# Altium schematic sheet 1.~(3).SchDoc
size 420 x 297 mm
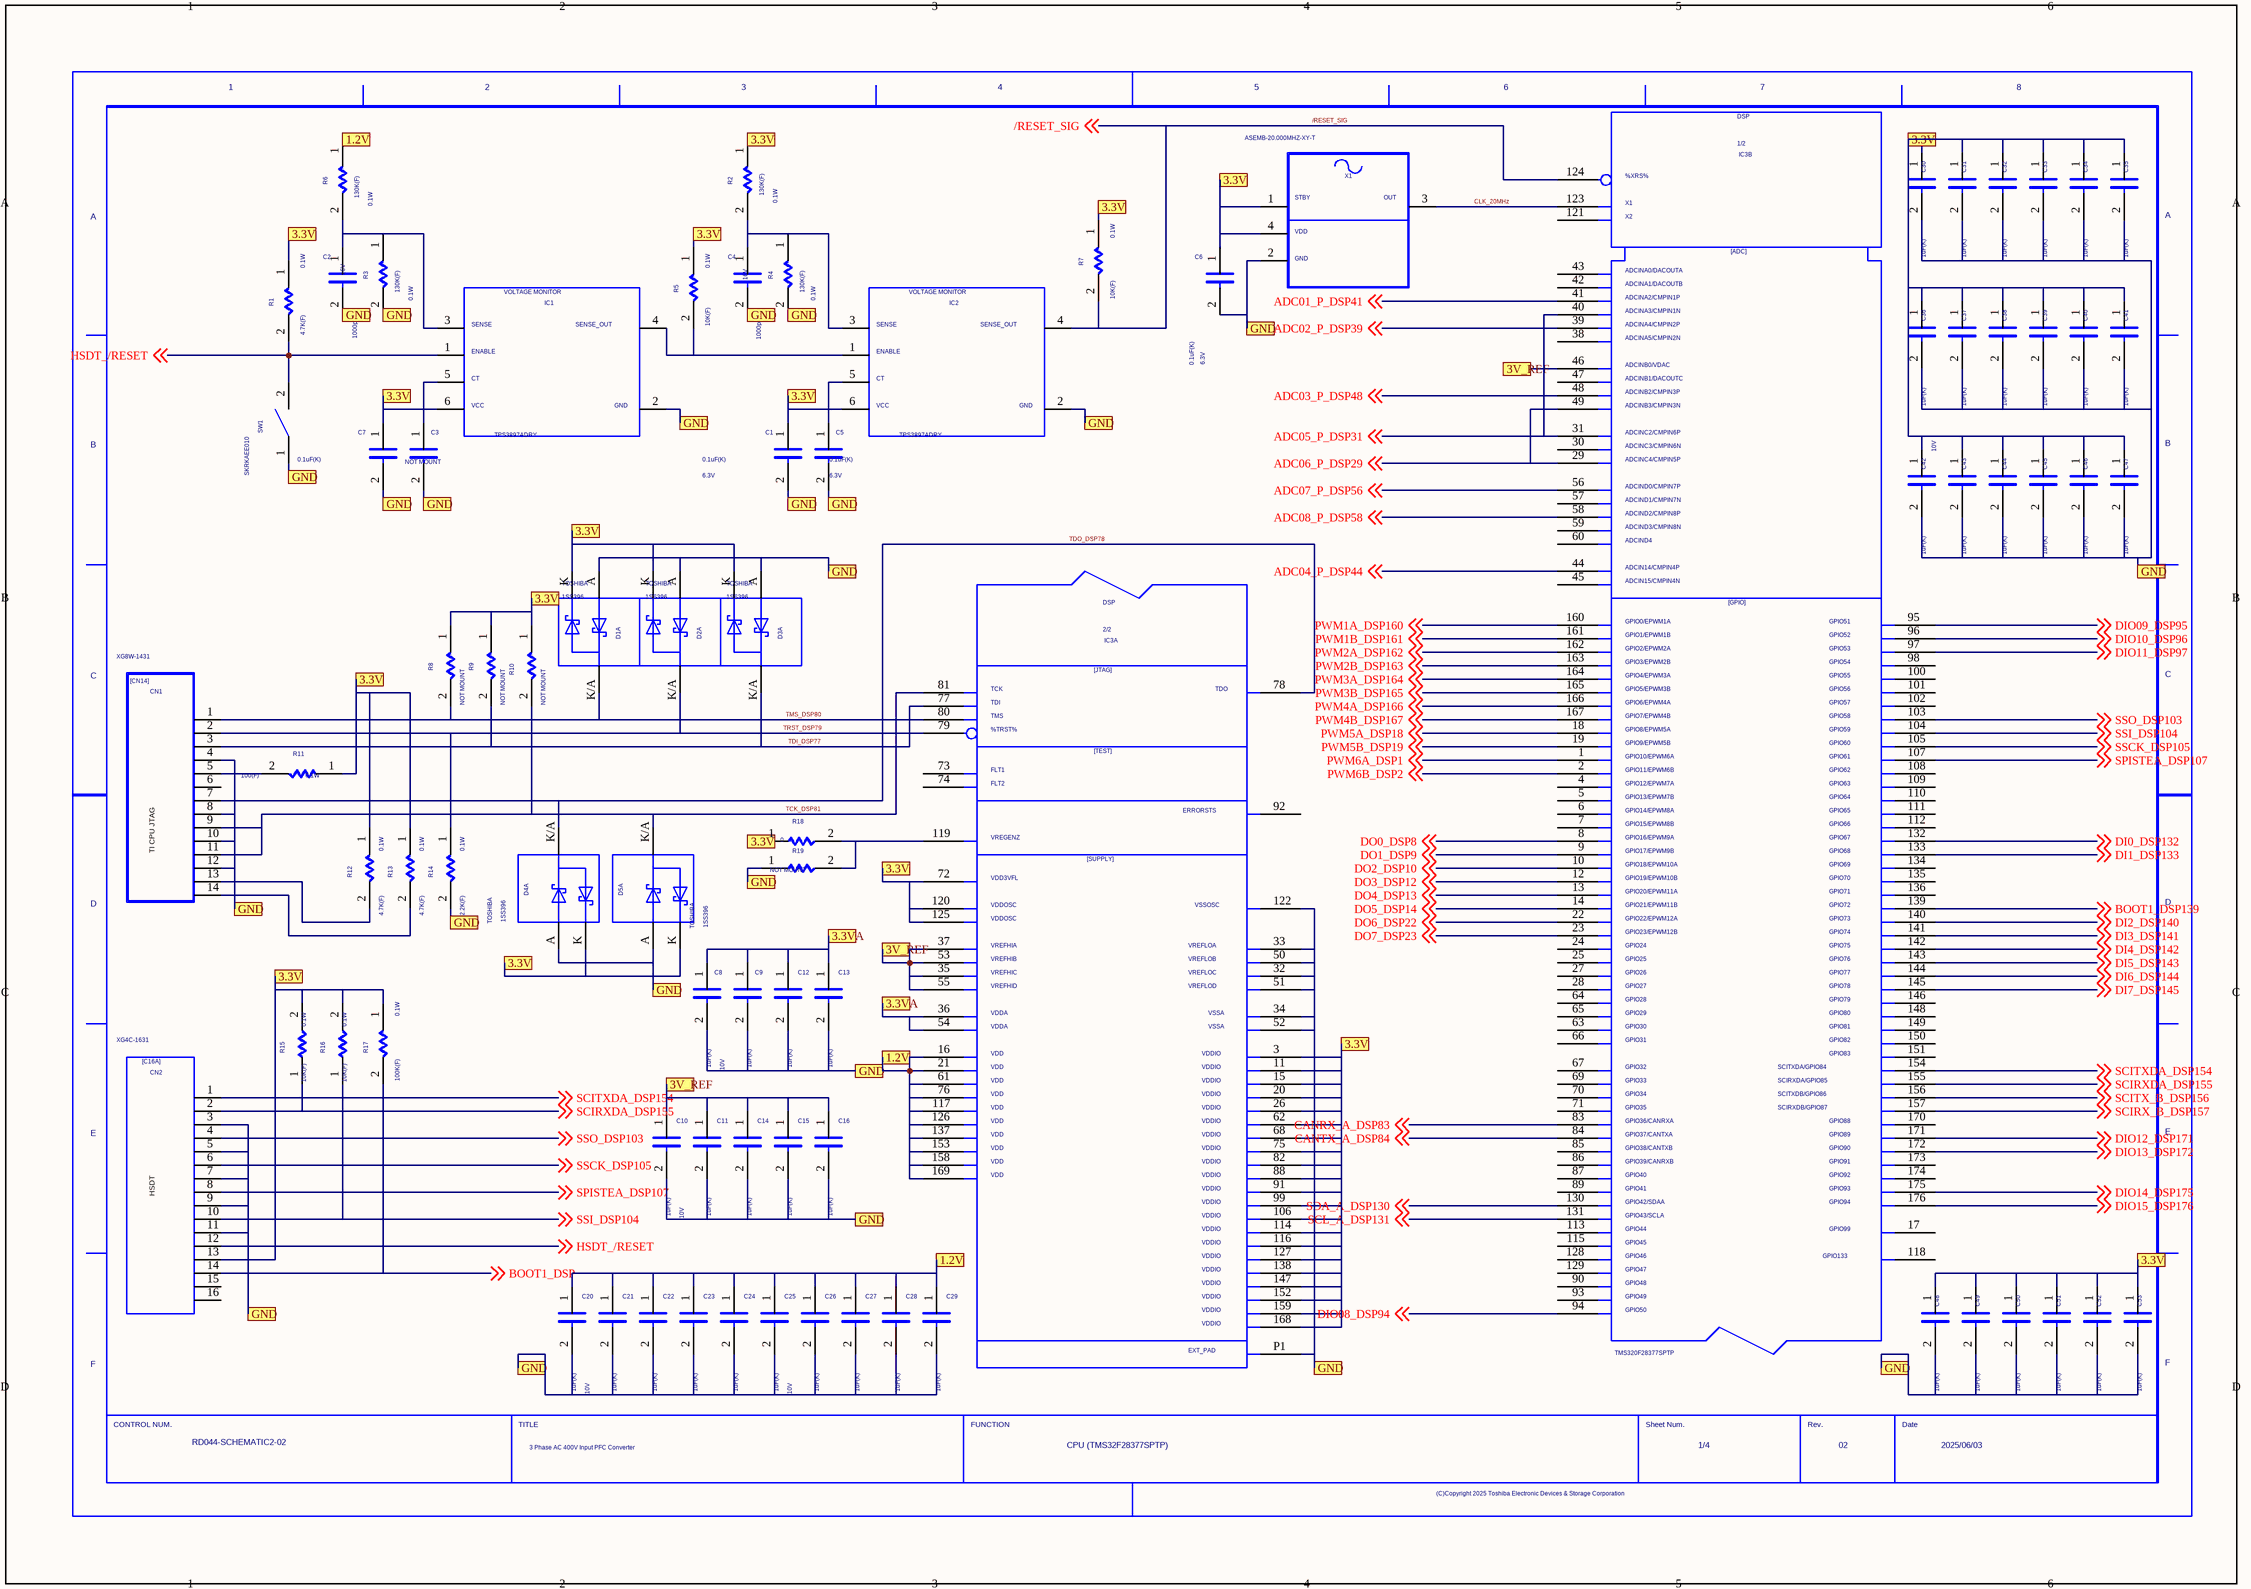
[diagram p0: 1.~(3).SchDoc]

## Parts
C1  VAL1: 0.1uF(K)  VAL2: 6.3V  (hidden comment: C)
C2  VAL1: 1000pF(K)  VAL2: 16V  (hidden comment: C)
C3  NOTMOUNT: NOT MOUNT  (hidden comment: C)
C4  VAL1: 1000pF(K)  VAL2: 16V  (hidden comment: C)
C5  VAL1: 0.1uF(K)  VAL2: 6.3V  (hidden comment: C)
C6  VAL1: 0.1uF(K)  VAL2: 6.3V  (hidden comment: C)
C7  VAL1: 0.1uF(K)  VAL2: 6.3V  (hidden comment: C)
C8  VAL1: 1uF(K)  VAL2: 10V  (hidden comment: C)
C9  VAL1: 1uF(K)  (hidden comment: C)
C10  VAL1: 1uF(K)  VAL2: 10V  (hidden comment: C)
C11  VAL1: 1uF(K)  (hidden comment: C)
C12  VAL1: 1uF(K)  (hidden comment: C)
C13  VAL1: 1uF(K)  (hidden comment: C)
C14  VAL1: 1uF(K)  (hidden comment: C)
C15  VAL1: 1uF(K)  (hidden comment: C)
C16  VAL1: 1uF(K)  (hidden comment: C)
C20  VAL1: 1uF(K)  VAL2: 10V  (hidden comment: C)
C21  VAL1: 1uF(K)  (hidden comment: C)
C22  VAL1: 1uF(K)  (hidden comment: C)
C23  VAL1: 1uF(K)  (hidden comment: C)
C24  VAL1: 1uF(K)  (hidden comment: C)
C25  VAL1: 1uF(K)  VAL2: 10V  (hidden comment: C)
C26  VAL1: 1uF(K)  (hidden comment: C)
C27  VAL1: 1uF(K)  (hidden comment: C)
C28  VAL1: 1uF(K)  (hidden comment: C)
C29  VAL1: 1uF(K)  (hidden comment: C)
C30  VAL1: 1uF(K)  (hidden comment: C)
C31  VAL1: 1uF(K)  (hidden comment: C)
C32  VAL1: 1uF(K)  (hidden comment: C)
C33  VAL1: 1uF(K)  (hidden comment: C)
C34  VAL1: 1uF(K)  (hidden comment: C)
C35  VAL1: 1uF(K)  (hidden comment: C)
C36  VAL1: 1uF(K)  (hidden comment: C)
C37  VAL1: 1uF(K)  (hidden comment: C)
C38  VAL1: 1uF(K)  (hidden comment: C)
C39  VAL1: 1uF(K)  (hidden comment: C)
C40  VAL1: 1uF(K)  (hidden comment: C)
C41  VAL1: 1uF(K)  (hidden comment: C)
C42  VAL1: 1uF(K)  VAL2: 10V  (hidden comment: C)
C43  VAL1: 1uF(K)  (hidden comment: C)
C44  VAL1: 1uF(K)  (hidden comment: C)
C45  VAL1: 1uF(K)  (hidden comment: C)
C46  VAL1: 1uF(K)  (hidden comment: C)
C47  VAL1: 1uF(K)  (hidden comment: C)
C48  VAL1: 1uF(K)  (hidden comment: C)
C49  VAL1: 1uF(K)  (hidden comment: C)
C50  VAL1: 1uF(K)  (hidden comment: C)
C51  VAL1: 1uF(K)  (hidden comment: C)
C52  VAL1: 1uF(K)  (hidden comment: C)
C53  VAL1: 1uF(K)  (hidden comment: C)
CN1  VAL3: XG8W-1431  (hidden comment: CN14)
CN2  VAL3: XG4C-1631  (hidden comment: C16A)
D1  USERCOMPTEXT3: TOSHIBA  (hidden comment: 1SS396)  (part A of 3)
D2  USERCOMPTEXT3: TOSHIBA  (hidden comment: 1SS396)  (part A of 3)
D3  USERCOMPTEXT3: TOSHIBA  (hidden comment: 1SS396)  (part A of 3)
D4  USERCOMPTEXT3: TOSHIBA  (hidden comment: 1SS396)  (part A of 3)
D5  USERCOMPTEXT3: TOSHIBA  (hidden comment: 1SS396)  (part A of 3)
IC1  VAL3: TPS3897ADRY  (hidden comment: TPS3897)
IC2  VAL3: TPS3897ADRY  (hidden comment: TPS3897)
IC3  U320F28377_1  (value not drawn)  (parts A,B of 2)
R1  VAL2: 0.1W  VAL1: 4.7K(F)  (hidden comment: R)
R2  VAL2: 0.1W  VAL1: 130K(F)  (hidden comment: R)
R3  VAL2: 0.1W  VAL1: 130K(F)  (hidden comment: R)
R4  VAL2: 0.1W  VAL1: 130K(F)  (hidden comment: R)
R5  VAL2: 0.1W  VAL1: 10K(F)  (hidden comment: R)
R6  VAL2: 0.1W  VAL1: 130K(F)  (hidden comment: R)
R7  VAL2: 0.1W  VAL1: 10K(F)  (hidden comment: R)
R8  NOTMOUNT: NOT MOUNT  (hidden comment: R)
R9  NOTMOUNT: NOT MOUNT  (hidden comment: R)
R10  NOTMOUNT: NOT MOUNT  (hidden comment: R)
R11  VAL2: 0.1W  VAL1: 100(F)  (hidden comment: R)
R12  VAL2: 0.1W  VAL1: 4.7K(F)  (hidden comment: R)
R13  VAL2: 0.1W  VAL1: 4.7K(F)  (hidden comment: R)
R14  VAL2: 0.1W  VAL1: 2.2K(F)  (hidden comment: R)
R15  VAL2: 0.1W  VAL1: 10K(F)  (hidden comment: R)
R16  VAL2: 0.1W  VAL1: 10K(F)  (hidden comment: R)
R17  VAL2: 0.1W  VAL1: 100K(F)  (hidden comment: R)
R18  VAL1: 0  (hidden comment: R)
R19  NOTMOUNT: NOT MOUNT  (hidden comment: R)
SW1  VAL3: SKRKAEE010  (hidden comment: SW)
U?  DATE: 2025/06/03  DRAWINGNUMBER: RD044-SCHEMATIC2-02  TITLE: 3 Phase AC 400V Input PFC Converter  FUNCTION: CPU (TMS32F28377SPTP)  SHEETNUMBER: 1/4  REVISION: 02  (hidden comment: WAKU_DEF100_2018)
X1  VAL3: ASEMB-20.000MHZ-XY-T  (hidden comment: ASEMB)

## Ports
1.2V, 3.3V, 3.3VA, 3V_REF, GND

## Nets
1.2V: C1.2 C2.2 C3.2 C4.2 C5.2 C6.2 C7.2 C8.2 C9.2 C10.2 C11.2 C12.2 C13.2 C14.2 C15.2 C16.2 C20.1 C20.2 C21.1 C21.2 C22.1 C22.2 C23.1 C23.2 C24.1 C24.2 C25.1 C25.2 C26.1 C26.2 C27.1 C27.2 C28.1 C28.2 C29.1 C29.2 C30.2 C31.2 C32.2 C33.2 C34.2 C35.2 C36.2 C37.2 C38.2 C39.2 C40.2 C41.2 C42.2 C43.2 C44.2 C45.2 C46.2 C47.2 C48.2 C49.2 C50.2 C51.2 C52.2 C53.2 CN1.4 CN1.8 CN1.10 CN1.12 CN2.3 CN2.5 CN2.7 CN2.9 CN2.11 D1.A D2.A D3.A D4.A D5.A IC1.2 IC2.2 IC3.16 IC3.21 IC3.32 IC3.33 IC3.34 IC3.50 IC3.51 IC3.52 IC3.61 IC3.76 IC3.117 IC3.122 IC3.126 IC3.137 IC3.153 IC3.158 IC3.169 IC3.P1 R3.2 R4.2 R6.1 R14.2 R19.1 SW1.1 X1.2 ; port GND, port 1.2V
3.3V: C1.1 C6.1 C7.1 C30.1 C31.1 C32.1 C33.1 C34.1 C35.1 C36.1 C37.1 C38.1 C39.1 C40.1 C41.1 C42.1 C43.1 C44.1 C45.1 C46.1 C47.1 C48.1 C49.1 C50.1 C51.1 C52.1 C53.1 CN2.13 D1.K D2.K D3.K D4.K D5.K IC1.6 IC2.6 IC3.3 IC3.11 IC3.15 IC3.20 IC3.26 IC3.62 IC3.68 IC3.72 IC3.75 IC3.82 IC3.88 IC3.91 IC3.99 IC3.106 IC3.114 IC3.116 IC3.120 IC3.125 IC3.127 IC3.138 IC3.147 IC3.152 IC3.159 IC3.168 R1.1 R2.1 R5.1 R7.1 R8.1 R9.1 R10.1 R11.1 R12.1 R13.1 R15.2 R16.2 R17.1 R18.1 X1.1 X1.4 ; port 3.3V
3.3VA: C8.1 C9.1 C12.1 C13.1 IC3.36 IC3.54 ; port 3.3VA
3V_REF: C10.1 C11.1 C14.1 C15.1 C16.1 IC3.35 IC3.37 IC3.46 IC3.53 IC3.55 ; port 3V_REF
/RESET_SIG: IC2.4 IC3.124 R7.2 ; off-sheet /RESET_SIG
ADC01_P_DSP41: IC3.41 ; off-sheet ADC01_P_DSP41
ADC02_P_DSP39: IC3.39 ; off-sheet ADC02_P_DSP39
ADC03_P_DSP48: IC3.48 ; off-sheet ADC03_P_DSP48
ADC04_P_DSP44: IC3.44 ; off-sheet ADC04_P_DSP44
ADC05_P_DSP31: IC3.31 IC3.40 ; off-sheet ADC05_P_DSP31
ADC06_P_DSP29: IC3.29 IC3.49 ; off-sheet ADC06_P_DSP29
ADC07_P_DSP56: IC3.56 ; off-sheet ADC07_P_DSP56
ADC08_P_DSP58: IC3.58 ; off-sheet ADC08_P_DSP58
BOOT1_DSP: CN2.14 R17.2 ; off-sheet BOOT1_DSP
BOOT1_DSP139: IC3.139 ; off-sheet BOOT1_DSP139
CANRX_A_DSP83: IC3.83 ; off-sheet CANRX_A_DSP83
CANTX_A_DSP84: IC3.84 ; off-sheet CANTX_A_DSP84
CLK_20MHz: IC3.123 X1.3
DI0_DSP132: IC3.132 ; off-sheet DI0_DSP132
DI1_DSP133: IC3.133 ; off-sheet DI1_DSP133
DI2_DSP140: IC3.140 ; off-sheet DI2_DSP140
DI3_DSP141: IC3.141 ; off-sheet DI3_DSP141
DI4_DSP142: IC3.142 ; off-sheet DI4_DSP142
DI5_DSP143: IC3.143 ; off-sheet DI5_DSP143
DI6_DSP144: IC3.144 ; off-sheet DI6_DSP144
DI7_DSP145: IC3.145 ; off-sheet DI7_DSP145
DIO08_DSP94: IC3.94 ; off-sheet DIO08_DSP94
DIO09_DSP95: IC3.95 ; off-sheet DIO09_DSP95
DIO10_DSP96: IC3.96 ; off-sheet DIO10_DSP96
DIO11_DSP97: IC3.97 ; off-sheet DIO11_DSP97
DIO12_DSP171: IC3.171 ; off-sheet DIO12_DSP171
DIO13_DSP172: IC3.172 ; off-sheet DIO13_DSP172
DIO14_DSP175: IC3.175 ; off-sheet DIO14_DSP175
DIO15_DSP176: IC3.176 ; off-sheet DIO15_DSP176
DO0_DSP8: IC3.8 ; off-sheet DO0_DSP8
DO1_DSP9: IC3.9 ; off-sheet DO1_DSP9
DO2_DSP10: IC3.10 ; off-sheet DO2_DSP10
DO3_DSP12: IC3.12 ; off-sheet DO3_DSP12
DO4_DSP13: IC3.13 ; off-sheet DO4_DSP13
DO5_DSP14: IC3.14 ; off-sheet DO5_DSP14
DO6_DSP22: IC3.22 ; off-sheet DO6_DSP22
DO7_DSP23: IC3.23 ; off-sheet DO7_DSP23
HSDT_/RESET: CN2.12 IC1.1 R1.2 SW1.2 ; off-sheet HSDT_/RESET
N16607086: IC1.4 IC2.1 R5.2
N16607090: C4.1 IC2.3 R2.2 R4.1
N16607182: C2.1 IC1.3 R3.1 R6.2
N16607210: C5.1 IC2.5
N16608626: CN1.5 R11.2
N16609034: CN1.13 R12.2
N16609038: CN1.14 R13.2
N16609736: IC3.119 R18.2 R19.2
PWM1A_DSP160: IC3.160 ; off-sheet PWM1A_DSP160
PWM1B_DSP161: IC3.161 ; off-sheet PWM1B_DSP161
PWM2A_DSP162: IC3.162 ; off-sheet PWM2A_DSP162
PWM2B_DSP163: IC3.163 ; off-sheet PWM2B_DSP163
PWM3A_DSP164: IC3.164 ; off-sheet PWM3A_DSP164
PWM3B_DSP165: IC3.165 ; off-sheet PWM3B_DSP165
PWM4A_DSP166: IC3.166 ; off-sheet PWM4A_DSP166
PWM4B_DSP167: IC3.167 ; off-sheet PWM4B_DSP167
PWM5A_DSP18: IC3.18 ; off-sheet PWM5A_DSP18
PWM5B_DSP19: IC3.19 ; off-sheet PWM5B_DSP19
PWM6A_DSP1: IC3.1 ; off-sheet PWM6A_DSP1
PWM6B_DSP2: IC3.2 ; off-sheet PWM6B_DSP2
SCIRX_B_DSP157: IC3.157 ; off-sheet SCIRX_B_DSP157
SCIRXDA_DSP155: CN2.2 IC3.155 R15.1 ; off-sheet SCIRXDA_DSP155
SCITX_B_DSP156: IC3.156 ; off-sheet SCITX_B_DSP156
SCITXDA_DSP154: CN2.1 IC3.154 ; off-sheet SCITXDA_DSP154
SCL_A_DSP131: IC3.131 ; off-sheet SCL_A_DSP131
SDA_A_DSP130: IC3.130 ; off-sheet SDA_A_DSP130
SIG15: C3.1 IC1.5
SPISTEA_DSP107: CN2.8 IC3.107 ; off-sheet SPISTEA_DSP107
SSCK_DSP105: CN2.6 IC3.105 ; off-sheet SSCK_DSP105
SSI_DSP104: CN2.10 IC3.104 R16.1 ; off-sheet SSI_DSP104
SSO_DSP103: CN2.4 IC3.103 ; off-sheet SSO_DSP103
TCK_DSP81: CN1.9 CN1.11 D5.K/A IC3.81 R10.2
TDI_DSP77: CN1.3 D3.K/A IC3.77 R9.2
TDO_DSP78: CN1.7 D4.K/A IC3.78
TMS_DSP80: CN1.1 D1.K/A IC3.80 R8.2
TRST_DSP79: CN1.2 D2.K/A IC3.79 R14.1

Not connected (* = marked no-connect by the designer): CN1 6; CN2 15 16; IC3 4 5 6 7 17 24 25 27 28 30 38 42 43 45 47 57 59 60 63 64 65 66 67 69 70 71 73 74 85 86 87 89 90 92 93 98 100 101 102 108 109 110 111 112 113 115 118 121 128 129 134 135 136 146 148 149 150 151 170 173 174

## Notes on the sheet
- (near CN1) TI CPU JTAG
- (near CN2) HSDT

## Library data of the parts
C1 C5-C7 = C: OriginalSymbolOrigin: (2540,7620); CDBNAME: C-GRM155R70J104KA01D; USERCOMPTEXT1: 1005
C2 C4 = C: OriginalSymbolOrigin: (2540,7620); CDBNAME: C-GRM188R71C102KA01D; USERCOMPTEXT1: 1608
C3 = C: OriginalSymbolOrigin: (2540,7620); CDBNAME: C-1608_NM; USERCOMPTEXT1: 1608
C8 C10 C20 C25 C42 = C: OriginalSymbolOrigin: (2540,7620); CDBNAME: C-GRM188R71A105KA61D; USERCOMPTEXT1: 1608
C9 C11-C16 C21-C24 C26-C41 C43-C53 = C: OriginalSymbolOrigin: (2540,7620); CDBNAME: C-GRM188R71A105KA61D
CN1 = CN14: OriginalSymbolOrigin: (2540,45720); CDBNAME: CN-XG8W-1431; MAXGCOUNT: 1; ADSCNVFLAG: ON
CN2 = C16A: SAVEAREA0: -32851,-599,52300,52191; TIME: 12:01:18; UPDATEUSER: fukuda-y; UPDATETIME: 13:44:49; SAVECOUNT: 2; OriginalSymbolOrigin: (2540,48260); CDBNAME: CN-XG4C-1631
D1-D5 = 1SS396: SAVECOUNT: 7; SAVEAREA0: -5465,-437,27678,21425; TIME: 18:51:12; UPDATEUSER: cae; UPDATETIME: 10:39:29; OriginalSymbolOrigin: (5080,17780); CDBNAME: D-1SS396_AK
IC1 IC2 = TPS3897: SAVEAREA0: -10817,-344,54055,33349; TIME: 16:54:57; UPDATEUSER: cae; UPDATETIME: 13:48:08; SAVECOUNT: 66; OriginalSymbolOrigin: (5080,30480); CDBNAME: IC-TPS3897ADRY
IC3 = U320F28377_1: SAVEAREA0: -157495,-2464,228972,238585; SAVECOUNT: 59; TIME: 10:04:23; UPDATEUSER: cae; UPDATETIME: 18:05:54; OriginalSymbolOrigin: (7620,233680); CaptureCellPackProp: U320F28377_1A; VAL3: TMS320F28377SPTP; FUNCN: TMS320F_2_function; CDBNAME: IC-TMS320F28377SPTP
R1 R12 R13 = R: OriginalSymbolOrigin: (5080,5080); CDBNAME: R-ERJ3EKF4701V; USERCOMPTEXT1: 1608
R2 = R: OriginalSymbolOrigin: (5080,5080); CDBNAME: R-ERA3AEB304V; USERCOMPTEXT1: 1608
R3 R17 = R: OriginalSymbolOrigin: (5080,5080); CDBNAME: R-ERJ3EKF1003V; USERCOMPTEXT1: 1608
R4 = R: OriginalSymbolOrigin: (5080,5080); CDBNAME: R-ERA3AEB563V; USERCOMPTEXT1: 1608
R5 R7 R15 R16 = R: OriginalSymbolOrigin: (5080,5080); CDBNAME: R-ERJ3EKF1002V; USERCOMPTEXT1: 1608
R6 = R: OriginalSymbolOrigin: (5080,5080); CDBNAME: R-ERA3AEB134V; USERCOMPTEXT1: 1608
R8-R10 R19 = R: OriginalSymbolOrigin: (5080,5080); CDBNAME: R-1608_NM; USERCOMPTEXT1: 1608
R11 = R: OriginalSymbolOrigin: (5080,5080); CDBNAME: R-ERJ3EKF1000V; USERCOMPTEXT1: 1608
R14 = R: OriginalSymbolOrigin: (5080,5080); CDBNAME: R-ERJ3EKF2201V; USERCOMPTEXT1: 1608
R18 = R: OriginalSymbolOrigin: (5080,5080); CDBNAME: R-RK73Z1JTTD
SW1 = SW: SAVEAREA0: -3361,-153,18383,13055; SAVECOUNT: 49; TIME: 15:02:55; UPDATEUSER: fukuda-y; UPDATETIME: 10:01:15; OriginalSymbolOrigin: (5080,5080); CDBNAME: SW-SKRKAEE010; MAXGCOUNT: 1; ADSCNVFLAG: ON
U? = WAKU_DEF100_2018: PLOTTIME: HH:MM; SAVEAREA0: -45080,-4508,463680,304612; TIME: 13:54:34; UPDATEUSER: e5025010; UPDATETIME: 15:56:23; SAVECOUNT: 4; OriginalSymbolOrigin: (10160,284480)
X1 = ASEMB: SAVEAREA0: -13388,-318,46493,30783; TIME: 14:56:21; UPDATEUSER: cae; UPDATETIME: 14:57:23; SAVECOUNT: 2; OriginalSymbolOrigin: (5080,27940); CDBNAME: X-ASEMB-20.000MHZ-XY-T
